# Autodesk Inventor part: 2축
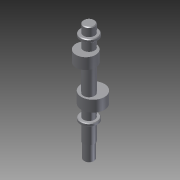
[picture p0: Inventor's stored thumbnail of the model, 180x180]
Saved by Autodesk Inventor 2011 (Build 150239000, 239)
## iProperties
Created: 2014-12
Part Number: 2축
Document SubType Name: Modeling
Designer: user
Density: 1 g/cm^3
Author: user
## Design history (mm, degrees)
sketch "스케치1"
  geometry: C1 r 7.5 at (0, 0); 1 further point
  constraints: 1 centre point, 1 coincident
  dimensions: "d0" = 15 diameter of C1
extrude "돌출1" new body sketch "스케치1" distance "d1" = 24; taper "d2" = 0 deg
sketch "스케치2"
  geometry: C1 r 7.5 at (0, 0) reference; C2 r 8.5 at (0, 0)
  constraints: 1 centre point, 1 coincident
  dimensions: "d3" = 17 diameter of C2
extrude "돌출2" join sketch "스케치2" distance "d4" = 27; taper "d5" = 0 deg
sketch "스케치3"
  geometry: C1 r 8.5 at (0, 0) reference; C2 r 13 at (0, 0)
  constraints: 1 centre point, 1 coincident
  dimensions: "d6" = 26 diameter of C2
extrude "돌출3" join sketch "스케치3" distance "d7" = 5; taper "d8" = 0 deg
sketch "스케치4"
  geometry: C1 r 13 at (0, 0) reference; C2 r 8.5 at (0, 0)
  constraints: 1 centre point, 1 coincident
  dimensions: "d9" = 17 diameter of C2
extrude "돌출4" join sketch "스케치4" distance "d10" = 14.5; taper "d11" = 0 deg
sketch "스케치5"
  geometry: C1 r 8.5 at (0, 0) reference; C2 r 17.5 at (0, 6)
  constraints: 1 centre point
  dimensions: "d12" = 35 diameter of C2; "d13" = 6 distance of C1.centre C2.centre
extrude "돌출5" join sketch "스케치5" distance "d14" = 17; taper "d15" = 0 deg
sketch "스케치6"
  geometry: C1 r 8.5 at (0, -6); 1 further point
  constraints: 1 centre point, 1 coincident
  dimensions: "d16" = 17 diameter of C1
extrude "돌출6" join sketch "스케치6" distance "d17" = 43; taper "d18" = 0 deg
sketch "스케치7"
  geometry: C1 r 8.5 at (0, 0) reference; C2 r 15 at (0, -5)
  constraints: 1 centre point
  dimensions: "d19" = 30 diameter of C2; "d20" = 5 distance of C1.centre C2.centre
extrude "돌출7" join sketch "스케치7" distance "d21" = 17; taper "d22" = 0 deg
sketch "스케치8"
  geometry: C1 r 8.5 at (0, 5); 1 further point
  constraints: 1 centre point, 1 coincident
  dimensions: "d23" = 17 diameter of C1
extrude "돌출8" join sketch "스케치8" distance "d24" = 14.5; taper "d25" = 0 deg
sketch "스케치9"
  geometry: C1 r 8.5 at (0, 0) reference; C2 r 13 at (0, 0)
  constraints: 1 centre point, 1 coincident
  dimensions: "d26" = 26 diameter of C2
extrude "돌출9" join sketch "스케치9" distance "d27" = 5; taper "d28" = 0 deg
sketch "스케치10"
  geometry: C1 r 13 at (0, 0) reference; C2 r 8.5 at (0, 0)
  constraints: 1 centre point, 1 coincident
  dimensions: "d29" = 17 diameter of C2
extrude "돌출10" join sketch "스케치10" distance "d30" = 13; taper "d31" = 0 deg
chamfer "모따기1" distance "d32" = 1; stored, may be unused: second distance "d33" = 2, angle "d34" = 45 deg
sketch "스케치11"
  geometry: L1 (-8.5, 70.5)-(-11.5, 70.5) reference; L2 (-11.5, 70.5)-(-11.5, 87.5) reference; L3 (-11.5, 87.5)-(-8.5, 87.5) reference; L4 (-8.5, 87.5)-(-8.5, 130.5) reference; L5 (-8.5, 130.5)-(-20, 130.5) reference; L6 (-20, 130.5)-(-20, 147.5) reference; L7 (-20, 147.5)-(-8.5, 147.5) reference; L8 (-8.5, 147.5)-(-8.5, 162) reference; L9 (-8.5, 162)-(-12, 162) reference; L10 (-12, 162)-(-13, 163) reference; L11 (-13, 163)-(-13, 166) reference; L12 (-13, 166)-(-12, 167) reference; L13 (-12, 167)-(-8.5, 167) reference; L14 (-8.5, 167)-(-8.5, 179) reference; L15 (-8.5, 179)-(-7.5, 180) reference; L16 (-7.5, 180)-(7.5, 180) reference; L17 (7.5, 180)-(8.5, 179) reference; L18 (8.5, 179)-(8.5, 167) reference; L19 (8.5, 167)-(12, 167) reference; L20 (12, 167)-(13, 166) reference; L21 (13, 166)-(13, 163) reference; L22 (13, 163)-(12, 162) reference; L23 (12, 162)-(8.5, 162) reference; L24 (8.5, 162)-(8.5, 147.5) reference; L25 (8.5, 147.5)-(10, 147.5) reference; L26 (10, 147.5)-(10, 130.5) reference; L27 (10, 130.5)-(8.5, 130.5) reference; L28 (8.5, 130.5)-(8.5, 87.5) reference; L29 (8.5, 87.5)-(23.5, 87.5) reference; L30 (23.5, 87.5)-(23.5, 70.5) reference; L31 (23.5, 70.5)-(8.5, 70.5) reference; L32 (8.5, 70.5)-(8.5, 56) reference; L33 (8.5, 56)-(12, 56) reference; L34 (12, 56)-(13, 55) reference; L35 (13, 55)-(13, 52) reference; L36 (13, 52)-(12, 51) reference; L37 (12, 51)-(8.5, 51) reference; L38 (8.5, 51)-(8.5, 24) reference; L39 (8.5, 24)-(7.5, 24) reference; L40 (7.5, 24)-(7.5, 1) reference; L41 (7.5, 1)-(6.5, 0) reference; L42 (6.5, 0)-(-6.5, 0) reference; L43 (-6.5, 0)-(-7.5, 1) reference; L44 (-7.5, 1)-(-7.5, 24) reference; L45 (-7.5, 24)-(-8.5, 24) reference; L46 (-8.5, 24)-(-8.5, 51) reference; L47 (-8.5, 51)-(-12, 51) reference; L48 (-12, 51)-(-13, 52) reference; L49 (-13, 52)-(-13, 55) reference; L50 (-13, 55)-(-12, 56) reference; L51 (-12, 56)-(-8.5, 56) reference; L52 (-8.5, 56)-(-8.5, 70.5) reference; L53 (12.292, -4.853)-(4.5, -4.853); L54 (4.5, -4.853)-(4.5, 20); L55 (4.5, 20)-(12.292, 20); L56 (12.292, 20)-(12.292, -4.853); 1 further point
  constraints: 8 end point, 2 parallel, 1 horizontal, 1 perpendicular
  dimensions: "d35" = 3 distance between parallel lines of L40 L54; "d36" = 20 distance between parallel lines of L42 L55
extrude "돌출11" cut sketch "스케치11" stored distance "d37" = 5; taper "d38" = 0 deg
fillet "모깎기1" dims "d39" = 2.5
node "솔리드1"
node "절단 모서리 투영1"
